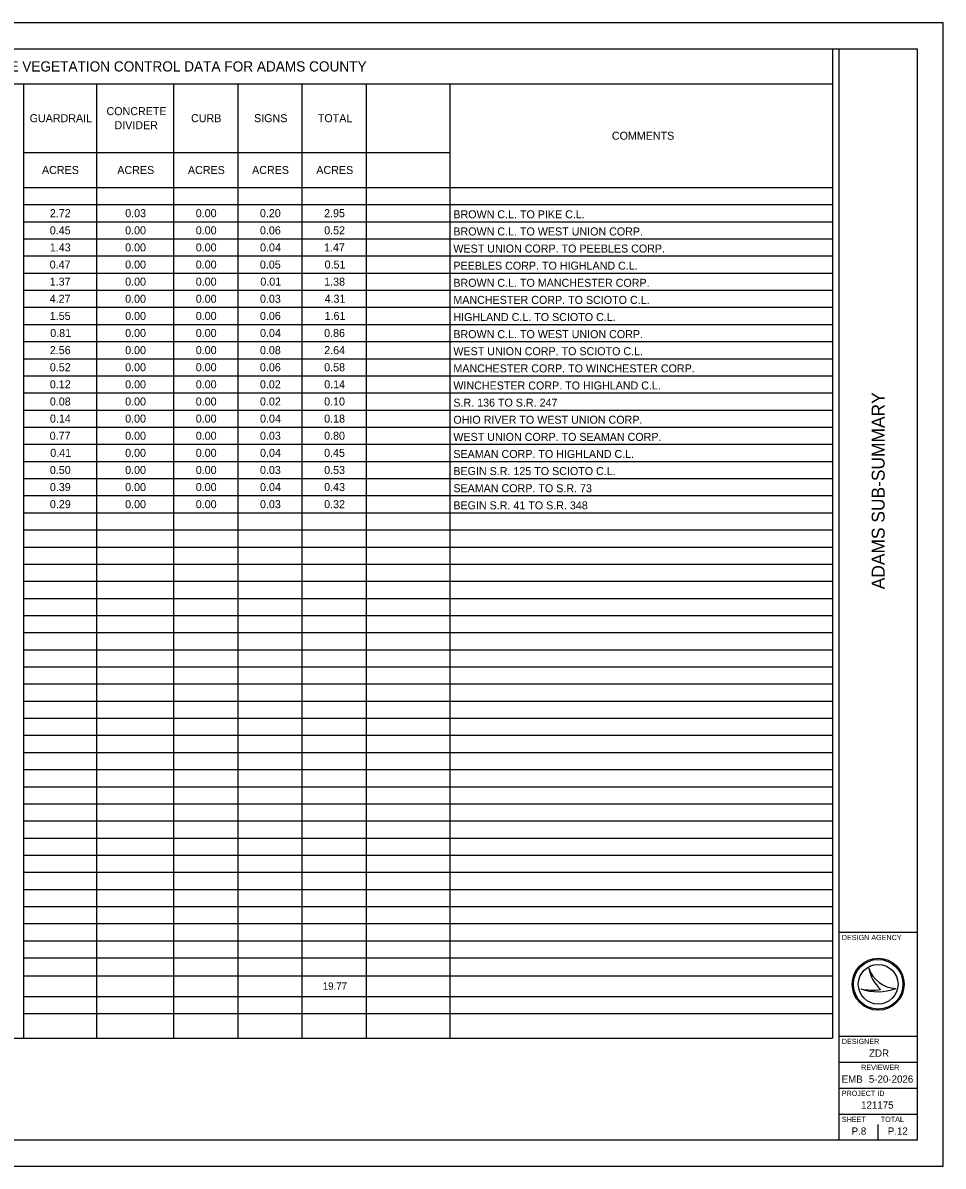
# Model space of a CAD drawing. Extents: x 0 to 34, y 0 to 22.
# Drawn here: x 16.29 to 34, y 0 to 22 of the extents above; entities that cross this region are included whole.
import ezdxf

# ---------------------------------------------------------------- set-up
doc = ezdxf.new("R2010")
doc.units = 0
for name, color, linetype in [('SH_Border', 7, 'Continuous'), ('SH_Cut_Line', 7, 'Continuous'), ('SH_Data', 7, 'Continuous'), ('SH_Text', 7, 'Continuous')]:
    doc.layers.add(name, color=color, linetype=linetype)

msp = doc.modelspace()

# ---------------------------------------------------------------- linework, layer by layer
at = {"layer": 'SH_Border'}
for p, q in [((32, 0.5), (32, 21.5)), ((32, 4.5), (33.5, 4.5)), ((32, 2.5), (33.5, 2.5)), ((32, 2), (33.5, 2)), ((32, 1.5), (33.5, 1.5)), ((32, 1), (33.5, 1))]:
    msp.add_line(p, q, dxfattribs=at)
msp.add_lwpolyline([(1.5, 21.5), (33.5, 21.5), (33.5, 0.5), (1.5, 0.5)], close=True, dxfattribs=at)
at = {"layer": 'SH_Cut_Line'}
msp.add_lwpolyline([(0, 0), (34, 0), (34, 22), (0, 22)], close=True, dxfattribs=at)
at = {"layer": 'SH_Data'}
for p, q in [((32.567, 3.81), (32.567, 3.81)), ((32.417, 3.41), (32.417, 3.41)), ((32.75, 3.5), (32.75, 3.5)), ((33.087, 3.419), (33.087, 3.419)), ((32.375, 0.675), (32.375, 0.675)), ((32.75, 0.5), (32.75, 0.8))]:
    msp.add_line(p, q, dxfattribs=at)
for radius in [0.5, 0.477, 0.477, 0.382]:
    msp.add_circle((32.75, 3.5), radius, dxfattribs=at)
for centre, radius, start, end in [((33.116, 3.998), 0.58, 198.9257, 198.9319), ((33.347, 3.97), 0.796, 191.6379, 191.6421), ((33.116, 3.998), 0.58, 198.9319, 267.1657), ((33.347, 3.97), 0.796, 191.6421, 226.0947), ((32.739, 4.37), 1.013, 251.4576, 290.0832), ((32.648, 4.654), 1.266, 259.4964, 259.4995), ((32.739, 4.37), 1.013, 251.4527, 251.4576), ((32.648, 4.654), 1.266, 259.4995, 276.6672)]:
    msp.add_arc(centre, radius, start, end, dxfattribs=at)
at = {"layer": 'SH_Text'}
for p, q in [((1.5, 21.5), (31.872, 21.5)), ((31.872, 21.5), (31.872, 2.46)), ((7.451, 20.825), (16.302, 20.825)), ((16.28, 20.825), (31.872, 20.825)), ((16.302, 20.825), (16.302, 2.46)), ((17.707, 20.825), (17.707, 2.46)), ((19.189, 20.825), (19.189, 2.46)), ((20.425, 20.825), (20.425, 2.46)), ((21.66, 20.825), (21.66, 2.46)), ((22.895, 20.825), (22.895, 2.46)), ((24.509, 20.825), (24.509, 2.46)), ((16.302, 19.507), (24.509, 19.507)), ((16.302, 18.832), (31.872, 18.832)), ((16.302, 18.502), (31.872, 18.502)), ((16.302, 18.173), (31.872, 18.173)), ((16.302, 17.844), (31.872, 17.844)), ((16.302, 17.514), (31.872, 17.514)), ((16.302, 17.185), (31.872, 17.185)), ((16.302, 16.855), (31.872, 16.855)), ((16.302, 16.526), (31.872, 16.526)), ((16.302, 16.196), (31.872, 16.196)), ((16.302, 15.867), (31.872, 15.867)), ((16.302, 15.538), (31.872, 15.538)), ((16.302, 15.208), (31.872, 15.208)), ((16.302, 14.879), (31.872, 14.879)), ((16.302, 14.549), (31.872, 14.549)), ((16.302, 14.22), (31.872, 14.22)), ((16.302, 13.891), (31.872, 13.891)), ((16.302, 13.561), (31.872, 13.561)), ((16.302, 13.232), (31.872, 13.232)), ((16.302, 12.902), (31.872, 12.902)), ((16.302, 12.573), (31.872, 12.573)), ((16.302, 12.244), (31.872, 12.244)), ((16.302, 11.914), (31.872, 11.914)), ((16.302, 11.585), (31.872, 11.585)), ((16.302, 11.255), (31.872, 11.255)), ((16.302, 10.926), (31.872, 10.926)), ((16.302, 10.596), (31.872, 10.596)), ((16.302, 10.267), (31.872, 10.267)), ((16.302, 9.938), (31.872, 9.938)), ((16.302, 9.608), (31.872, 9.608)), ((16.302, 9.279), (31.872, 9.279)), ((16.302, 8.949), (31.872, 8.949)), ((16.302, 8.62), (31.872, 8.62)), ((16.302, 8.291), (31.872, 8.291)), ((16.302, 7.961), (31.872, 7.961)), ((16.302, 7.632), (31.872, 7.632)), ((16.302, 7.302), (31.872, 7.302)), ((16.302, 6.973), (31.872, 6.973)), ((16.302, 6.644), (31.872, 6.644)), ((16.302, 6.314), (31.872, 6.314)), ((16.302, 5.985), (31.872, 5.985)), ((16.302, 5.655), (31.872, 5.655)), ((16.302, 5.326), (31.872, 5.326)), ((16.302, 4.996), (31.872, 4.996)), ((16.302, 4.667), (31.872, 4.667)), ((16.302, 4.338), (31.872, 4.338)), ((16.302, 4.008), (31.872, 4.008)), ((16.302, 3.662), (31.872, 3.662)), ((16.302, 3.267), (31.872, 3.267)), ((16.302, 2.938), (31.872, 2.938)), ((7.451, 2.46), (16.302, 2.46)), ((16.28, 2.46), (31.872, 2.46))]:
    msp.add_line(p, q, dxfattribs=at)

# ---------------------------------------------------------------- texts
at = {"layer": 'SH_Data'}
msp.add_text('ADAMS SUB-SUMMARY', height=0.25, rotation=90, dxfattribs=at).set_placement((32.875, 11.101))
for s, height, p in [('DESIGN AGENCY', 0.1, (32.05, 4.35)), ('DESIGNER', 0.1, (32.05, 2.35)), ('ZDR', 0.14, (32.575, 2.105)), ('REVIEWER', 0.1, (32.422, 1.85)), ('EMB', 0.14, (32.047, 1.605)), ('5-20-2026', 0.14, (32.571, 1.605)), ('PROJECT ID', 0.1, (32.05, 1.35)), ('121175', 0.14, (32.421, 1.105)), ('SHEET', 0.1, (32.05, 0.85)), ('TOTAL', 0.1, (32.8, 0.85)), ('P.8', 0.14, (32.239, 0.605)), ('P.12', 0.14, (32.935, 0.605))]:
    msp.add_text(s, height=height, dxfattribs=at).set_placement(p)
at = {"layer": 'SH_Text'}
for s, height, p in [('HERBICIDAL SPRAYING NONSELECTIVE VEGETATION CONTROL DATA FOR ADAMS COUNTY', 0.196, (11.109, 21.064)), ('GUARDRAIL', 0.154, (16.421, 20.089)), ('CONCRETE', 0.154, (17.9, 20.224)), ('CURB', 0.154, (19.528, 20.089)), ('SIGNS', 0.154, (20.74, 20.089)), ('TOTAL', 0.154, (21.967, 20.089)), ('DIVIDER', 0.154, (18.054, 19.954)), ('COMMENTS', 0.154, (27.625, 19.751)), ('ACRES', 0.154, (16.659, 19.092)), ('ACRES', 0.154, (18.108, 19.092)), ('ACRES', 0.154, (19.467, 19.092)), ('ACRES', 0.154, (20.702, 19.092)), ('ACRES', 0.154, (21.938, 19.092)), ('2.72', 0.154, (16.81, 18.261)), ('0.03', 0.154, (18.26, 18.261)), ('0.00', 0.154, (19.618, 18.261)), ('0.20', 0.154, (20.853, 18.261)), ('2.95', 0.154, (22.088, 18.261)), ('BROWN C.L. TO PIKE C.L.', 0.154, (24.575, 18.239)), ('0.45', 0.154, (16.809, 17.931)), ('0.00', 0.154, (18.259, 17.931)), ('0.00', 0.154, (19.618, 17.931)), ('0.06', 0.154, (20.853, 17.931)), ('0.52', 0.154, (22.089, 17.931)), ('BROWN C.L. TO WEST UNION CORP.', 0.154, (24.575, 17.909)), ('1.43', 0.154, (16.81, 17.602)), ('0.00', 0.154, (18.259, 17.602)), ('0.00', 0.154, (19.618, 17.602)), ('0.04', 0.154, (20.855, 17.602)), ('1.47', 0.154, (22.086, 17.602)), ('WEST UNION CORP. TO PEEBLES CORP.', 0.154, (24.575, 17.58)), ('0.47', 0.154, (16.807, 17.272)), ('0.00', 0.154, (18.259, 17.272)), ('0.00', 0.154, (19.618, 17.272)), ('0.05', 0.154, (20.852, 17.272)), ('0.51', 0.154, (22.097, 17.272)), ('PEEBLES CORP. TO HIGHLAND C.L.', 0.154, (24.575, 17.251)), ('1.37', 0.154, (16.807, 16.943)), ('0.00', 0.154, (18.259, 16.943)), ('0.00', 0.154, (19.618, 16.943)), ('0.01', 0.154, (20.861, 16.943)), ('1.38', 0.154, (22.089, 16.943)), ('BROWN C.L. TO MANCHESTER CORP.', 0.154, (24.575, 16.921)), ('4.27', 0.154, (16.807, 16.614)), ('0.00', 0.154, (18.259, 16.614)), ('0.00', 0.154, (19.618, 16.614)), ('0.03', 0.154, (20.854, 16.614)), ('4.31', 0.154, (22.097, 16.614)), ('MANCHESTER CORP. TO SCIOTO C.L.', 0.154, (24.575, 16.592)), ('1.55', 0.154, (16.809, 16.284)), ('0.00', 0.154, (18.259, 16.284)), ('0.00', 0.154, (19.618, 16.284)), ('0.06', 0.154, (20.853, 16.284)), ('1.61', 0.154, (22.097, 16.284)), ('HIGHLAND C.L. TO SCIOTO C.L.', 0.154, (24.575, 16.262)), ('0.81', 0.154, (16.818, 15.955)), ('0.00', 0.154, (18.259, 15.955)), ('0.00', 0.154, (19.618, 15.955)), ('0.04', 0.154, (20.855, 15.955)), ('0.86', 0.154, (22.088, 15.955)), ('BROWN C.L. TO WEST UNION CORP.', 0.154, (24.575, 15.933)), ('2.56', 0.154, (16.809, 15.625)), ('0.00', 0.154, (18.259, 15.625)), ('0.00', 0.154, (19.618, 15.625)), ('0.08', 0.154, (20.853, 15.625)), ('2.64', 0.154, (22.09, 15.625)), ('WEST UNION CORP. TO SCIOTO C.L.', 0.154, (24.575, 15.604)), ('0.52', 0.154, (16.81, 15.296)), ('0.00', 0.154, (18.259, 15.296)), ('0.00', 0.154, (19.618, 15.296)), ('0.06', 0.154, (20.853, 15.296)), ('0.58', 0.154, (22.089, 15.296)), ('MANCHESTER CORP. TO WINCHESTER CORP.', 0.154, (24.575, 15.274)), ('0.12', 0.154, (16.81, 14.967)), ('0.00', 0.154, (18.259, 14.967)), ('0.00', 0.154, (19.618, 14.967)), ('0.02', 0.154, (20.853, 14.967)), ('0.14', 0.154, (22.09, 14.967)), ('WINCHESTER CORP. TO HIGHLAND C.L.', 0.154, (24.575, 14.945)), ('0.08', 0.154, (16.81, 14.637)), ('0.00', 0.154, (18.259, 14.637)), ('0.00', 0.154, (19.618, 14.637)), ('0.02', 0.154, (20.853, 14.637)), ('0.10', 0.154, (22.088, 14.637)), ('S.R. 136 TO S.R. 247', 0.154, (24.575, 14.615)), ('0.14', 0.154, (16.812, 14.308)), ('0.00', 0.154, (18.259, 14.308)), ('0.00', 0.154, (19.618, 14.308)), ('0.04', 0.154, (20.855, 14.308)), ('0.18', 0.154, (22.089, 14.308)), ('OHIO RIVER TO WEST UNION CORP.', 0.154, (24.575, 14.286)), ('0.77', 0.154, (16.807, 13.978)), ('0.00', 0.154, (18.259, 13.978)), ('0.00', 0.154, (19.618, 13.978)), ('0.03', 0.154, (20.854, 13.978)), ('0.80', 0.154, (22.088, 13.978)), ('WEST UNION CORP. TO SEAMAN CORP.', 0.154, (24.575, 13.956)), ('0.41', 0.154, (16.818, 13.649)), ('0.00', 0.154, (18.259, 13.649)), ('0.00', 0.154, (19.618, 13.649)), ('0.04', 0.154, (20.855, 13.649)), ('0.45', 0.154, (22.088, 13.649)), ('SEAMAN CORP. TO HIGHLAND C.L.', 0.154, (24.575, 13.627)), ('0.50', 0.154, (16.81, 13.319)), ('0.00', 0.154, (18.259, 13.319)), ('0.00', 0.154, (19.618, 13.319)), ('0.03', 0.154, (20.854, 13.319)), ('0.53', 0.154, (22.089, 13.319)), ('BEGIN S.R. 125 TO SCIOTO C.L.', 0.154, (24.575, 13.298)), ('0.39', 0.154, (16.811, 12.99)), ('0.00', 0.154, (18.259, 12.99)), ('0.00', 0.154, (19.618, 12.99)), ('0.04', 0.154, (20.855, 12.99)), ('0.43', 0.154, (22.089, 12.99)), ('SEAMAN CORP. TO S.R. 73', 0.154, (24.575, 12.968)), ('0.29', 0.154, (16.811, 12.661)), ('0.00', 0.154, (18.259, 12.661)), ('0.00', 0.154, (19.618, 12.661)), ('0.03', 0.154, (20.854, 12.661)), ('0.32', 0.154, (22.089, 12.661)), ('BEGIN S.R. 41 TO S.R. 348', 0.154, (24.575, 12.639)), ('19.77', 0.14, (22.061, 3.395))]:
    msp.add_text(s, height=height, dxfattribs=at).set_placement(p)

doc.saveas('drawing.dxf')
